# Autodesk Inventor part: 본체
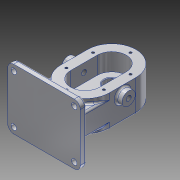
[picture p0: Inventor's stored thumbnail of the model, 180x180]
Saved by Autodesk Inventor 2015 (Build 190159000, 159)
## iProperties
Created: 2020-09
Part Number: 본체
Material: 알루미늄 6061
Document SubType Name: Modeling
Designer: LINEART-SSD.D4.16.04
Density: 2.7 g/cm^3
Appearance: 알루미늄 - 평지
Mass: 1438.7 g
Surface Area: 781.105 cm^2
Volume: 532.85 cm^3
Author: LINEART-SSD.D4.16.04
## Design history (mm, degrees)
sketch "스케치1"
  geometry: L1 (0, 0)-(0, 44); L2 (-40, 0)-(-40, 44); L3 (40, 44)-(40, 0); L4 (0, 0)-(0, 44); L5 (-24, 0)-(-24, 44); L6 (24, 44)-(24, 0); A1 r 40 centre (0, 0) between (-40, 0) and (40, 0); A2 r 40 centre (0, 44) between (40, 44) and (-40, 44); A3 r 24 centre (0, 0) between (-24, 0) and (24, 0); A4 r 24 centre (0, 44) between (24, 44) and (-24, 44); 2 further points
  constraints: 16 end point, 8 point on circle, 8 tangent, 4 centre point, 2 midpoint, 2 parallel, 2 vertical
  dimensions: "d0" = 44 distance of L1.start L1.end; "d1" = 40 radius of A2; "d2" = 24 radius of A4
extrude "돌출1" new body sketch "스케치1" distance "d3" = 53; taper "d4" = 0 deg
extrude "돌출2" join sketch "스케치1" distance "d5" = 24; taper "d6" = 0 deg
sketch "스케치2"
  geometry: C1 r 12.5 at (0, 0); C2 r 12.5 at (0, 44); A1 r 40 centre (0, 44) between (40, 44) and (-40, 44) reference; 1 further point
  constraints: 2 centre point, 2 coincident
  dimensions: "d7" = 25 diameter of C1; "d8" = 25 diameter of C2
extrude "돌출3" cut sketch "스케치2" distance "d9" = 15; taper "d10" = 0 deg
sketch "스케치3"
  geometry: C1 r 8.5 at (0, 0); 1 further point
  constraints: 1 centre point
  dimensions: "d11" = 17 diameter of C1
sketch "스케치4"
  geometry: C1 r 19 at (0, 44); A1 r 40 centre (0, 44) between (40, 44) and (-40, 44) reference; 1 further point
  constraints: 1 centre point, 1 coincident
  dimensions: "d12" = 38 diameter of C1
extrude "돌출4" join sketch "스케치4" distance "d13" = 17; taper "d14" = 0 deg
sketch "스케치5"
  geometry: C1 r 14 at (0, 0); 1 further point
  constraints: 1 centre point
  dimensions: "d15" = 28 diameter of C1
extrude "돌출5" cut sketch "스케치5" distance "d16" = 7.3; taper "d17" = 0 deg
extrude "돌출6" cut sketch "스케치3" stored distance "d18" = 7.3; taper "d19" = 0 deg
sketch "스케치7"
  geometry: L1 (-53, 0)-(-53, 44) reference; L2 (0, 0)-(-53, 0) reference; L3 (0, 44)-(0, 0) reference; L4 (0, 84)-(-53, 84) reference; L5 (0, -40)-(-53, -40) reference; L6 (-53, 44)-(-53, 0) reference; L7 (-53, 22)-(-39, 22); C1 r 11 at (-39, 22)
  constraints: 2 end point, 1 centre point, 1 coincident, 1 horizontal, 1 midpoint
  dimensions: "d20" = 14 distance of L7.start L7.end; "d21" = 22 diameter of C1
extrude "돌출7" join sketch "스케치7" distance "d22" = 10; taper "d23" = 0 deg
node "작업 평면1"
sketch "스케치8"
  geometry: L1 (-40, 0)-(40, 0) reference; L2 (40, 0)-(40, 53) reference; L3 (40, 53)-(-40, 53) reference; L4 (-40, 0)-(-40, 53) reference; L5 (-19, -17)-(19, -17) reference; L6 (0, -17)-(-60, -17); L7 (-60, -17)-(60, -17); L8 (60, -17)-(60, 83); L9 (60, 83)-(-60, 83); L10 (-60, 83)-(-60, -17); 1 further point
  constraints: 10 end point, 2 parallel, 1 horizontal, 1 midpoint, 1 perpendicular, 1 point on line
  dimensions: "d25" = 60 distance of L6.start L6.end; "d26" = 120 distance of L9.end L8.end; "d27" = 100 distance of L8.end L7.end
extrude "돌출8" join sketch "스케치8" distance "d28" = 10; taper "d29" = 0 deg
node "작업 평면2"
sketch "스케치9"
  geometry: L1 (60, -68)-(-60, -68) reference; L2 (-60, -68)-(-60, -58) reference; L3 (60, -58)-(-60, -58) reference; L4 (60, -68)-(60, -58) reference; L5 (60, -58)-(-60, -58) reference; L6 (0, -58)-(-40, -58); L7 (0, -58)-(40, -58); L8 (40, -58)-(40, 0); L9 (-40, -58)-(-40, 0); L10 (-40, 0)-(-17.911, -27.515); L11 (-17.911, -27.515)-(15.056, -27.515); L12 (15.056, -27.515)-(40, 0); A1 r 40 centre (0, 0) between (-40, 0) and (40, 0) reference; 1 further point
  constraints: 14 end point, 2 point on line, 1 midpoint, 1 perpendicular
  dimensions: "d30" = 40 distance of L6.start L6.end; "d31" = 40 distance of L6.start L7.end; "d32" = 47.8057 deg angle of L3 L12; "d33" = 51.2428 deg angle of L3 L10; "d34" = 30.48466 distance from line of L3.start L11
extrude "돌출9" join sketch "스케치9" stored distance "d35" = 37; taper "d36" = 0 deg
hole "구멍1" diameter "d39" = 8.376; stored, may be unused: countersink angle "d43" = 90 deg, drill point angle "d45" = 118 deg; dims "d40" = 40, "d41" = 4, "d42" = 2, "d44" = 47.3, "d101" = 10, "d102" = 10
hole "구멍2" diameter "d48" = 8.376; stored, may be unused: countersink angle "d52" = 90 deg, drill point angle "d54" = 118 deg; dims "d49" = 50, "d50" = 4, "d51" = 2, "d53" = 27.3, "d103" = 10, "d104" = 10
sketch "스케치11" dims "d57" = 31
  geometry: L1 (0, 0)-(0, 44); L2 (0, 0)-(0, -31); 1 further point
  constraints: 6 end point, 2 vertical, 1 coincident, 1 midpoint, 1 vertical alignment, 2 other
hole "구멍3" sketch "스케치11" at (0, -31) diameter "d58" = 4.134; stored, may be unused: countersink angle "d62" = 90 deg, drill point angle "d64" = 118 deg; dims "d59" = 10, "d60" = 4, "d61" = 2, "d63" = 12
sketch "스케치12"
  geometry: L1 (0, -31)-(0, 75); L2 (0, 75)-(0, 44); L3 (0, 44)-(31, 44); L4 (0, 44)-(-31, 44); L5 (0, 0)-(31, 0); L6 (0, 0)-(-31, 0); C1 r 2.067 at (0, -31) reference; A1 r 31 centre (0, 44) between (31, 44) and (-31, 44); A2 r 31 centre (0, 0) between (31, 0) and (-31, 0); 1 further point
  constraints: 12 end point, 4 horizontal, 4 point on circle, 2 centre point, 2 coincident, 1 point on line, 1 vertical
  dimensions: "d65" = 106 distance of L1.start L1.end; "d66" = 31 distance of L1.end L2.end; "d67" = 31 radius of A1; "d68" = 31 radius of A2
hole "구멍4" sketch "스케치12" at (-31, 44), (-31, 0), (31, 0), (31, 44), (0, 75) diameter "d69" = 4.134; stored, may be unused: countersink angle "d73" = 90 deg, drill point angle "d75" = 118 deg; dims "d70" = 10, "d71" = 4, "d72" = 2, "d74" = 12
sketch "스케치13"
  geometry: L1 (60, 17)-(-60, 17) reference; L2 (-60, -83)-(60, -83) reference; L3 (-60, 17)-(-50, 17); L4 (-50, 17)-(-50, 7); L5 (-60, -83)-(-50, -83); L6 (-50, -83)-(-50, -73); L7 (-50, -73)-(-60, -73); L8 (-60, -73)-(-60, -83); C1 r 4.5 at (-50, 7); C2 r 4.5 at (-50, -73); 1 further point
  constraints: 12 end point, 2 centre point, 2 parallel, 2 perpendicular, 1 coincident, 1 horizontal, 1 point on line
  dimensions: "d76" = 10 distance of L1.end L3.end; "d77" = 10 distance of L3.end L4.end; "d79" = 9 diameter of C1; "d80" = 10 distance from line of C1.centre L1; "d81" = 0 distance from line of C1.centre L4; "d85" = 10 distance of L7.end L6.end; "d86" = 10 distance of L6.end L5.end; "d87" = 9 diameter of C2
extrude "돌출10" cut sketch "스케치13" stored distance "d82" = 37; taper "d83" = 0 deg
fillet "모깎기1" dims "d84" = 10
extrude "돌출11" cut sketch "스케치13" stored distance "d88" = 37; taper "d89" = 0 deg
node "작업 평면4"
fillet "모깎기2" dims "d90" = 10
chamfer "모따기1" distance "d91" = 1; stored, may be unused: second distance "d92" = 2, angle "d93" = 45 deg
chamfer "모따기2" distance "d94" = 1; stored, may be unused: second distance "d95" = 2, angle "d96" = 45 deg
fillet "모깎기3" dims "d97" = 3
fillet "모깎기4" dims "d98" = 0.5
fillet "모깎기6" dims "d100" = 3
sketch "스케치16"
  geometry: L1 (-50, -83)-(50, -83) reference; L2 (-60, 7)-(-60, -73) reference; 2 further points
  constraints: 1 other
  dimensions: "d105" = 12 distance from line of L1 point (0, -71); "d106" = 60 distance from line of L2 point (0, -71)
feature "엠보싱1" sketch "스케치16" dims "d0" = 44, "d1" = 40, "d2" = 24, "d107" = 0.5, "d108" = 0
node "솔리드1"
mirror "대칭1"
mirror "대칭2"
node "투영된 루프1"
other parameters: "d24" = -68
